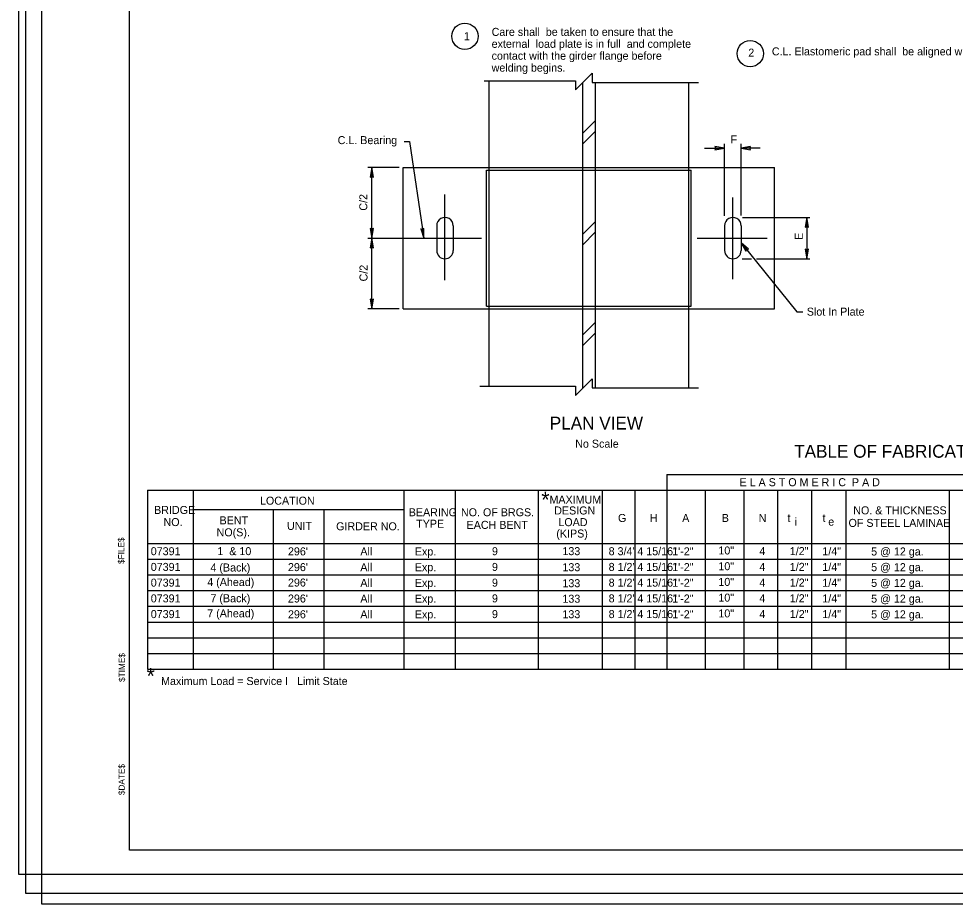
# Model space of a CAD drawing. Extents: x -194 to 226, y 505 to 725.
# Drawn here: x -193.6 to -47.4, y 505.4 to 643.6 of the extents above; entities that cross this region are included whole.
import ezdxf

# ---------------------------------------------------------------- set-up
doc = ezdxf.new("R2010")
doc.units = 0
for name, color, linetype in [('border', 7, 'Continuous'), ('Border 2660-Hwy18 - Level 62', 7, 'Continuous'), ('Border 2660-Hwy18 - Level 63', 7, 'Continuous'), ('Level 20', 7, 'Continuous'), ('Level 31', 7, 'Continuous'), ('Level 40', 7, 'Continuous'), ('Level 41', 7, 'Continuous'), ('Level 42', 7, 'Continuous'), ('Level 43', 7, 'Continuous'), ('Level 62 PDF', 7, 'Continuous')]:
    doc.layers.add(name, color=color, linetype=linetype)

msp = doc.modelspace()

# ---------------------------------------------------------------- linework, layer by layer
at = {"layer": 'border'}
for p, q in [((-176.33, 513.86), (-176.33, 719.31)), ((143.78, 513.86), (-176.33, 513.86))]:
    msp.add_line(p, q, dxfattribs=at)
at = {"layer": 'Border 2660-Hwy18 - Level 62'}
msp.add_lwpolyline([(-192.53, 725.17), (148.65, 725.17), (148.65, 507.07), (-192.53, 507.07)], close=True, dxfattribs=at)
at = {"layer": 'Border 2660-Hwy18 - Level 63'}
msp.add_lwpolyline([(-193.64, 723.74), (146.35, 723.74), (146.35, 510.04), (-193.64, 510.04)], close=True, dxfattribs=at)
at = {"layer": 'Level 20'}
for p, q in [((-127.1, 602.8), (-127.1, 616.17)), ((-82.15, 602.94), (-82.15, 615.72)), ((-139.16, 609.37), (-121.39, 609.37)), ((-87.71, 609.37), (-76.8, 609.37))]:
    msp.add_line(p, q, dxfattribs=at)
at = {"layer": 'Level 31'}
for p, q in [((-120.21, 586.27), (-120.21, 633.94)), ((-105.61, 633.62), (-105.61, 585.93)), ((-103.64, 633.66), (-103.64, 585.98)), ((-89.04, 585.98), (-89.04, 633.66)), ((-133.6, 598.35), (-133.6, 620.39)), ((-133.6, 620.39), (-120.21, 620.39)), ((-120.61, 598.74), (-120.61, 620)), ((-120.61, 620), (-88.65, 620)), ((-120.21, 620.39), (-89.04, 620.39)), ((-89.04, 620.39), (-75.66, 620.39)), ((-88.65, 598.74), (-88.65, 620)), ((-75.66, 598.35), (-75.66, 620.39)), ((-128.39, 611.3), (-128.39, 607.44)), ((-125.82, 611.3), (-125.82, 607.44)), ((-83.44, 611.3), (-83.44, 607.44)), ((-80.87, 611.3), (-80.87, 607.44)), ((-133.6, 598.35), (-120.21, 598.35)), ((-120.61, 598.74), (-88.65, 598.74)), ((-120.21, 598.35), (-89.04, 598.35)), ((-89.04, 598.35), (-75.66, 598.35))]:
    msp.add_line(p, q, dxfattribs=at)
for centre, start, end in [((-127.1, 611.3), 0, 180.0422), ((-82.15, 611.3), 0, 180.0422), ((-127.1, 607.44), 180.0422, 0), ((-82.15, 607.44), 180.0422, 0)]:
    msp.add_arc(centre, 1.29, start, end, dxfattribs=at)
at = {"layer": 'Level 40'}
for p, q in [((-166.4, 570.01), (-166.4, 542.09)), ((-133.5, 570.01), (-133.5, 542.09)), ((-125.49, 570.01), (-125.49, 542.09)), ((-112.53, 570.01), (-112.53, 542.09)), ((-102.55, 570.01), (-102.55, 542.09)), ((-97.43, 570.01), (-97.43, 542.09)), ((-86.47, 570.01), (-86.47, 542.09)), ((-80.45, 570.01), (-80.45, 542.09)), ((-75.17, 570.01), (-75.17, 542.09)), ((-69.89, 570.01), (-69.89, 542.09)), ((-64.51, 570.01), (-64.51, 542.09)), ((-48.37, 570.01), (-48.37, 542.09)), ((-102.55, 567.56), (-102.55, 547)), ((-166.4, 567.03), (-133.5, 567.03)), ((-153.9, 567.03), (-153.9, 542.09)), ((-146, 567.03), (-146, 542.09)), ((-173.56, 561.72), (58.08, 561.72)), ((-173.56, 559.27), (58.08, 559.27)), ((-173.56, 556.81), (58.08, 556.81)), ((-173.56, 556.81), (58.08, 556.81)), ((-173.56, 554.36), (58.08, 554.36)), ((-173.56, 554.36), (58.08, 554.36)), ((-173.56, 551.91), (58.08, 551.91)), ((-173.56, 551.91), (58.08, 551.91)), ((-173.56, 549.45), (58.08, 549.45)), ((-173.56, 547), (58.08, 547)), ((-173.56, 544.54), (58.08, 544.54))]:
    msp.add_line(p, q, dxfattribs=at)
for centre in [(-123.98, 640.87), (-79.43, 638.17)]:
    msp.add_circle(centre, 2.05, dxfattribs=at)
at = {"layer": 'Level 41'}
for p, q in [((-92.48, 572.46), (-92.48, 542.09)), ((-92.48, 572.46), (58.08, 572.46)), ((-173.56, 570.01), (58.08, 570.01)), ((-173.56, 570.01), (-173.56, 542.09)), ((-173.56, 542.09), (58.08, 542.09))]:
    msp.add_line(p, q, dxfattribs=at)
at = {"layer": 'Level 42'}
for p, q in [((-105.61, 625.71), (-103.64, 627.67)), ((-105.61, 624.03), (-103.64, 626.02)), ((-105.61, 609.96), (-103.64, 611.93)), ((-105.61, 608.28), (-103.64, 610.28)), ((-105.61, 594.22), (-103.64, 596.19)), ((-105.61, 592.54), (-103.64, 594.53))]:
    msp.add_line(p, q, dxfattribs=at)
at = {"layer": 'Level 43'}
for p, q in [((-86.59, 623.42), (-83.44, 623.42)), ((-83.44, 612.86), (-83.44, 624.07)), ((-80.87, 612.91), (-80.87, 624.07)), ((-77.9, 623.42), (-80.87, 623.42)), ((-134.24, 620.39), (-139.16, 620.39)), ((-138.52, 609.37), (-138.52, 620.39)), ((-80.62, 612.59), (-70.14, 612.59)), ((-70.59, 612.59), (-70.59, 606.16)), ((-138.52, 598.35), (-138.52, 609.37)), ((-80.71, 606.16), (-79.23, 606.16)), ((-78.47, 606.16), (-70.14, 606.16)), ((-134.24, 598.35), (-139.16, 598.35))]:
    msp.add_line(p, q, dxfattribs=at)
for points in [[(-121, 633.94), (-106.74, 633.94), (-106.74, 632.5), (-104.11, 635.11), (-104.11, 633.66), (-87.51, 633.66)], [(-133.48, 624.45), (-132.64, 624.45), (-130.42, 609.37)], [(-80.87, 608.64), (-72.15, 597.88), (-71.24, 597.88)], [(-121.67, 586.27), (-106.74, 586.27), (-106.74, 584.81), (-104.11, 587.42), (-104.11, 585.98), (-87.51, 585.98)]]:
    msp.add_lwpolyline(points, dxfattribs=at)
for points in [[(-83.44, 623.42), (-84.94, 623.67), (-84.81, 623.42), (-84.94, 623.17)], [(-80.87, 623.42), (-79.37, 623.17), (-79.5, 623.42), (-79.37, 623.67)], [(-138.52, 620.39), (-138.77, 618.89), (-138.52, 619.02), (-138.27, 618.89)], [(-70.59, 612.59), (-70.84, 611.09), (-70.59, 611.22), (-70.34, 611.09)], [(-138.52, 609.37), (-138.27, 610.87), (-138.52, 610.74), (-138.77, 610.87)], [(-130.42, 609.37), (-130.39, 610.89), (-130.62, 610.73), (-130.89, 610.82)], [(-138.52, 609.37), (-138.77, 607.87), (-138.52, 608), (-138.27, 607.87)], [(-80.87, 608.64), (-80.12, 607.31), (-80, 607.57), (-79.73, 607.63)], [(-70.59, 606.16), (-70.34, 607.66), (-70.59, 607.53), (-70.84, 607.66)], [(-138.52, 598.35), (-138.27, 599.85), (-138.52, 599.72), (-138.77, 599.85)]]:
    msp.add_lwpolyline(points, close=True, dxfattribs=at)
at = {"layer": 'Level 62 PDF'}
msp.add_lwpolyline([(-190.03, 723.5), (151.15, 723.5), (151.15, 505.41), (-190.03, 505.41)], close=True, dxfattribs=at)

# ---------------------------------------------------------------- texts
at = {"layer": 'border'}
for s, p in [('$FILE$', (-177.16, 558.52)), ('$TIME$', (-177.06, 540.11)), ('$DATE$', (-177.1, 522.44))]:
    msp.add_text(s, height=0.96, rotation=89.9999, dxfattribs=at).set_placement(p)
at = {"layer": 'Level 40'}
for s, height, p in [('Care shall  be taken to ensure that the', 1.25, (-119.81, 640.93)), ('1', 1.25, (-124.14, 640.26)), ('external  load plate is in full  and complete', 1.25, (-119.81, 639.07)), ('C.L. Elastomeric pad shall  be aligned with C.L. Girder.', 1.25, (-76.06, 637.89)), ('contact with the girder flange before', 1.25, (-119.81, 637.21)), ('2', 1.25, (-79.74, 637.69)), ('welding begins.', 1.25, (-119.81, 635.35)), ('C.L. Bearing', 1.25, (-143.85, 624.04)), ('F', 1.25, (-82.51, 624.14)), ('Slot In Plate', 1.25, (-70.6, 597.27)), ('No Scale', 1.25, (-106.76, 576.66)), ('E L A S T O M E R I C  P A D', 1.25, (-81.11, 570.65)), ('LOCATION', 1.25, (-155.98, 567.77)), ('*', 2.5, (-112.06, 567.3)), ('MAXIMUM', 1.25, (-110.78, 567.94)), ('BRIDGE', 1.25, (-172.51, 566.32)), ('DESIGN', 1.25, (-110.04, 566.24)), ('NO. & THICKNESS', 1.25, (-63.35, 566.26)), ('BENT', 1.25, (-162.29, 564.7)), ('BEARING', 1.25, (-132.75, 565.96)), ('NO. OF BRGS.', 1.25, (-124.6, 565.96)), ('G', 1.25, (-100.08, 565.07)), ('H', 1.25, (-95.11, 565.07)), ('A', 1.25, (-90.06, 565.07)), ('B', 1.25, (-83.88, 565.07)), ('N', 1.25, (-78.12, 565.07)), ('t ', 1.25, (-73.63, 565.07)), ('t ', 1.25, (-68.15, 565.07)), ('NO.', 1.25, (-171.04, 564.43)), ('UNIT', 1.25, (-151.76, 563.83)), ('GIRDER NO.', 1.25, (-144.09, 563.77)), ('TYPE', 1.25, (-131.59, 564.17)), ('EACH BENT', 1.25, (-123.72, 563.99)), ('LOAD', 1.25, (-109.39, 564.42)), ('i', 1.25, (-72.52, 564.49)), ('e', 1.25, (-67.25, 564.49)), ('OF STEEL LAMINAE', 1.25, (-64.09, 564.3)), ('NO(S).', 1.25, (-162.75, 562.83)), ('(KIPS)', 1.25, (-109.71, 562.64)), ('07391', 1.25, (-173.03, 559.88)), ('1  & 10', 1.25, (-162.63, 559.89)), ("296'", 1.25, (-151.61, 559.86)), ('All', 1.25, (-140.31, 559.84)), ('Exp.', 1.25, (-131.8, 559.84)), ('9', 1.25, (-119.76, 559.88)), ('133', 1.25, (-108.76, 559.89)), ('8 3/4"', 1.25, (-101.54, 559.88)), ('4 15/16"', 1.25, (-97.06, 559.88)), ('1\'-2"', 1.25, (-91.62, 559.86)), ('10"', 1.25, (-84.41, 560)), ('4', 1.25, (-78.01, 559.9)), ('1/2"', 1.25, (-73.26, 559.9)), ('1/4"', 1.25, (-68.18, 559.87)), ('5 @ 12 ga.', 1.25, (-60.56, 559.84)), ('07391', 1.25, (-173.03, 557.43)), ('4 (Back)', 1.25, (-163.71, 557.34)), ("296'", 1.25, (-151.61, 557.4)), ('All', 1.25, (-140.31, 557.39)), ('Exp.', 1.25, (-131.8, 557.39)), ('9', 1.25, (-119.76, 557.43)), ('133', 1.25, (-108.76, 557.39)), ('8 1/2"', 1.25, (-101.54, 557.43)), ('4 15/16"', 1.25, (-97.06, 557.43)), ('1\'-2"', 1.25, (-91.62, 557.4)), ('10"', 1.25, (-84.41, 557.54)), ('4', 1.25, (-78.01, 557.44)), ('1/2"', 1.25, (-73.26, 557.44)), ('1/4"', 1.25, (-68.18, 557.42)), ('5 @ 12 ga.', 1.25, (-60.56, 557.39)), ('07391', 1.25, (-173.03, 554.98)), ('4 (Ahead)', 1.25, (-164.21, 555.07)), ("296'", 1.25, (-151.61, 554.99)), ('All', 1.25, (-140.31, 554.94)), ('Exp.', 1.25, (-131.8, 554.94)), ('9', 1.25, (-119.76, 554.98)), ('133', 1.25, (-108.76, 554.89)), ('8 1/2"', 1.25, (-101.54, 554.98)), ('4 15/16"', 1.25, (-97.06, 554.98)), ('1\'-2"', 1.25, (-91.62, 554.95)), ('10"', 1.25, (-84.41, 555.09)), ('4', 1.25, (-78.01, 554.99)), ('1/2"', 1.25, (-73.26, 554.99)), ('1/4"', 1.25, (-68.18, 554.96)), ('5 @ 12 ga.', 1.25, (-60.56, 554.94)), ('07391', 1.25, (-173.03, 552.52)), ('7 (Back)', 1.25, (-163.71, 552.54)), ("296'", 1.25, (-151.61, 552.5)), ('All', 1.25, (-140.31, 552.48)), ('Exp.', 1.25, (-131.8, 552.48)), ('9', 1.25, (-119.76, 552.52)), ('133', 1.25, (-108.76, 552.47)), ('8 1/2"', 1.25, (-101.54, 552.52)), ('4 15/16"', 1.25, (-97.06, 552.52)), ('1\'-2"', 1.25, (-91.62, 552.5)), ('10"', 1.25, (-84.41, 552.64)), ('4', 1.25, (-78.01, 552.54)), ('1/2"', 1.25, (-73.26, 552.54)), ('1/4"', 1.25, (-68.18, 552.51)), ('5 @ 12 ga.', 1.25, (-60.56, 552.48)), ('07391', 1.25, (-173.03, 550.07)), ('7 (Ahead)', 1.25, (-164.21, 550.19)), ("296'", 1.25, (-151.61, 550.04)), ('All', 1.25, (-140.31, 550.03)), ('Exp.', 1.25, (-131.8, 550.03)), ('9', 1.25, (-119.76, 550.07)), ('133', 1.25, (-108.76, 550.05)), ('8 1/2"', 1.25, (-101.54, 550.07)), ('4 15/16"', 1.25, (-97.06, 550.07)), ('1\'-2"', 1.25, (-91.62, 550.04)), ('10"', 1.25, (-84.41, 550.18)), ('4', 1.25, (-78.01, 550.08)), ('1/2"', 1.25, (-73.26, 550.08)), ('1/4"', 1.25, (-68.18, 550.06)), ('5 @ 12 ga.', 1.25, (-60.56, 550.03)), ('*', 2.5, (-173.69, 539.79)), ('Maximum Load = Service I   Limit State', 1.25, (-171.42, 539.62))]:
    msp.add_text(s, height=height, dxfattribs=at).set_placement(p)
for s, p in [('C/2', (-139.22, 613.65)), ('E', (-71.24, 609.09)), ('C/2', (-139.19, 602.61))]:
    msp.add_text(s, height=1.25, rotation=90, dxfattribs=at).set_placement(p)
at = {"layer": 'Level 41'}
for s, p in [(' PLAN VIEW ', (-111.48, 579.5)), (' TABLE OF FABRICATOR VARIABLES ', (-73.32, 575.1))]:
    msp.add_text(s, height=2, dxfattribs=at).set_placement(p)

doc.saveas('drawing.dxf')
